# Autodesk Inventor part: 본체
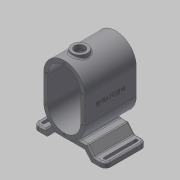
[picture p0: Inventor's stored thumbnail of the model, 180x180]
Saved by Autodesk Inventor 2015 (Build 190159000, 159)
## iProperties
Created: 2016-12
Part Number: 본체
Material: 일반
Document SubType Name: Modeling
Designer: mduedu
Density: 1 g/cm^3
Appearance: 기본값
Author: mduedu
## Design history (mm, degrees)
sketch "스케치1"
  geometry: L1 (40, -25)-(40, 25); L2 (-40, 25)-(-40, -25); L3 (-40, -25)-(40, 25); L4 (40, -25)-(-40, 25); L5 (0, 25)-(0, -25); A1 r 40 centre (0, 25) between (40, 25) and (-40, 25); A2 r 40 centre (0, -25) between (-40, -25) and (40, -25); 1 further point
  constraints: 10 end point, 4 point on circle, 3 tangent, 2 centre point, 2 midpoint, 2 parallel, 1 vertical
  dimensions: "d0" = 130 dimension on A2 A1; "d2" = 80 distance between parallel lines of L1 L2
extrude "돌출1" new body sketch "스케치1" stored distance "d3" = 100; taper "d4" = 0 deg
feature "쉘1" dims "d5" = 8
sketch "스케치15"
  geometry: L1 (-35, -64.5)-(35, -64.5); L2 (-35, -64.5)-(-47.586, -79.5); L3 (-47.586, -79.5)-(-70, -79.5); L4 (0, -64.5)-(0, 0); L5 (35, -64.5)-(47.586, -79.5); L6 (47.586, -79.5)-(70, -79.5); L7 (70, -89.5)-(42.923, -89.5); L8 (42.923, -89.5)-(30.337, -74.5); L9 (30.337, -74.5)-(-30.337, -74.5); L10 (-30.337, -74.5)-(-42.923, -89.5); L11 (-42.923, -89.5)-(-70, -89.5); L12 (-70, -79.5)-(-70, -89.5); L13 (70, -79.5)-(70, -89.5); A1 r 40 centre (0, -25) between (-40, -25) and (40, -25) reference; 1 further point
  constraints: 26 end point, 2 parallel, 2 perpendicular, 2 symmetric about line, 1 coincident, 1 horizontal, 1 midpoint, 1 vertical, 4 other
  dimensions: "d83" = 10 distance between parallel lines of L9 L1; "d85" = 140 distance between parallel lines of L13 L12; "d86" = 70 distance of L1.start L1.end; "d87" = 25 distance between parallel lines of L11 L1; "d88" = 130 deg angle of L1 L2; "d106" = 0.5 distance edge to line of A1 L1
extrude "돌출6" new body sketch "스케치15" stored distance "d89" = 80; taper "d90" = 0 deg
fillet "모깎기13" dims "d101" = 3
fillet "모깎기15" dims "d103" = 3
fillet "모깎기16" dims "d104" = 10
fillet "모깎기17" dims "d105" = 3
feature "결합2"
  node "솔리드2"
fillet "모깎기18" dims "d107" = 3
sketch "스케치16"
  geometry: L1 (8.015, 67)-(8.015, 7); L2 (14.015, 67)-(14.015, 7); A1 r 10 centre (11.015, 67) between (21.015, 67) and (11.015, 77) reference; A2 r 10 centre (11.015, 7) between (11.015, -3) and (21.015, 7) reference; A3 r 3 centre (11.015, 67) between (8.015, 67) and (14.015, 67); A4 r 3 centre (11.015, 7) between (8.015, 7) and (14.015, 7); 1 further point
  constraints: 4 end point, 4 point on circle, 4 tangent, 2 centre point, 2 coincident
  dimensions: "d108" = 6 diameter of A3; "d109" = 6 diameter of A4
extrude "돌출7" cut sketch "스케치16" stored distance "d110" = 80; taper "d111" = 0 deg
node "작업 평면1"
sketch "스케치9"
  geometry: 1 further point
sketch "스케치7"
  geometry: L1 (40, 50)-(-40, 50) reference; C1 r 15 at (0, 20); 1 further point
  constraints: 1 centre point, 1 vertical alignment
  dimensions: "d40" = 30 diameter of C1; "d41" = 30 distance from line of C1.centre L1
extrude "돌출4" join sketch "스케치7" stored distance "d42" = 80; taper "d43" = 0 deg
hole "구멍2" diameter "d46" = 20; stored, may be unused: countersink angle "d50" = 90 deg, drill point angle "d52" = 118 deg; dims "d44" = 10, "d45" = 10, "d47" = 6, "d48" = 4, "d49" = 2, "d51" = 8
fillet "모깎기4" dims "d53" = 3
node "작업 평면2"
sketch "스케치8"
  geometry: C1 r 15 at (0, 0) reference; C2 r 15 at (0, 0); 1 further point
  constraints: 1 centre point, 1 coincident
  dimensions: "d55" = 30 diameter of C2
extrude "돌출5" cut sketch "스케치8" stored distance "d56" = 80; taper "d57" = 0 deg
chamfer "모따기1" distance "d58" = 1; stored, may be unused: second distance "d59" = 2, angle "d60" = 45 deg
sketch "스케치10"
  geometry: 2 further points
  constraints: 1 coincident, 1 other
feature "엠보싱1" sketch "스케치10" dims "d0" = 130, "d2" = 80, "d61" = 0.5, "d62" = 0
sketch "스케치11"
  geometry: 1 further point
  constraints: 1 other
hole "구멍3" sketch "스케치11" at (0, 60) diameter "d63" = 3.242; stored, may be unused: countersink angle "d67" = 90 deg, drill point angle "d69" = 120 deg; dims "d64" = 8.6, "d65" = 4, "d66" = 2, "d68" = 10.6
sketch "스케치12"
  geometry: 1 further point
  constraints: 1 other
hole "구멍5" sketch "스케치12" at (0, 60) diameter "d70" = 3.242; stored, may be unused: countersink angle "d74" = 90 deg, drill point angle "d76" = 120 deg; dims "d71" = 8.6, "d72" = 4, "d73" = 2, "d75" = 10.6
node "솔리드1"
mirror "대칭2"
pattern_linear "직사각형 패턴1"
pattern_linear "직사각형 패턴2"
sketch "스케치13"
  geometry: L1 (-40, 25)-(-40, -25) reference; L2 (40, -25)-(40, 25) reference; L3 (35, 25)-(35, -25); L4 (-35, -25)-(-35, 25); A1 r 40 centre (0, 25) between (40, 25) and (-40, 25) reference; A2 r 40 centre (0, -25) between (-40, -25) and (40, -25) reference; A3 r 35 centre (0, 25) between (35, 25) and (-35, 25); A4 r 35 centre (0, -25) between (-35, -25) and (35, -25); 2 further points
  constraints: 5 point on circle, 4 end point, 2 centre point, 3 other
  dimensions: "d77" = 5 distance between parallel lines of L3 L2
sketch "스케치14"
  geometry: L1 (-40, 25)-(-40, -25) reference; L2 (40, -25)-(40, 25) reference; L3 (35, 25)-(35, -25); L4 (-35, -25)-(-35, 25); A1 r 40 centre (0, 25) between (40, 25) and (-40, 25) reference; A2 r 40 centre (0, -25) between (-40, -25) and (40, -25) reference; A3 r 35 centre (0, 25) between (35, 25) and (-35, 25); A4 r 35 centre (0, -25) between (-35, -25) and (35, -25); 2 further points
  constraints: 5 point on circle, 4 end point, 2 centre point, 3 other
  dimensions: "d80" = 5 distance between parallel lines of L2 L3
other parameters: "d54" = -8
